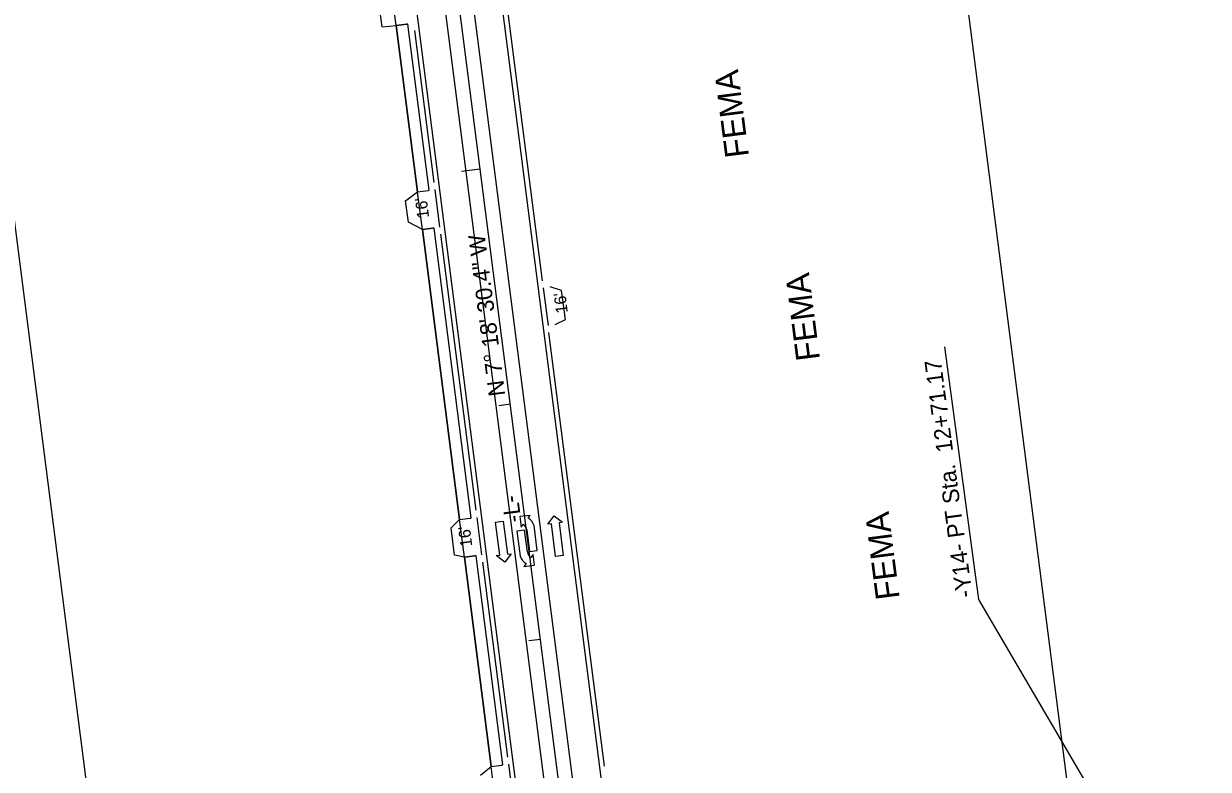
# Model space of a CAD drawing. Extents: x 2367848 to 2369479, y 800728 to 808616.
# Drawn here: x 2368272.3 to 2368772.3, y 807053 to 807367.5 of the extents above; entities that cross this region are included whole.
import ezdxf

# ---------------------------------------------------------------- set-up
doc = ezdxf.new("R2010")
doc.units = 0
for name, color, linetype in [('Default', 7, 'Continuous'), ('Prop Conc 2ft 6in Curb and Gutter', 7, 'Continuous'), ('Prop Conc 4in Sidewalk', 7, 'Continuous'), ('Prop Conc Drive Radius Type', 7, 'Continuous'), ('Prop Conc Driveway', 7, 'Continuous'), ('Prop Dimension', 7, 'Continuous'), ('Prop EOT', 7, 'Continuous'), ('Prop Horizontal Alignment', 7, 'Continuous'), ('Prop Horizontal Alignment Direction Label', 7, 'Continuous'), ('Prop Horizontal Alignment Station Label', 7, 'Continuous'), ('Prop Horizontal Alignment Tick Large', 7, 'Continuous'), ('Prop Horizontal Alignment Tick Small', 7, 'Continuous'), ('Prop Lane Arrow CELL', 7, 'Continuous'), ('Prop Lane Lines', 7, 'Continuous'), ('Prop Shade Light', 7, 'Continuous')]:
    doc.layers.add(name, color=color, linetype=linetype)

msp = doc.modelspace()

# ---------------------------------------------------------------- linework, layer by layer
at = {"layer": 'Default'}
msp.add_lwpolyline([(2368314.5, 806925.55), (2368228.68, 807594.69), (2368635.74, 807646.9), (2368721.56, 806977.76)], close=True, dxfattribs=at)
at = {"layer": 'Prop Conc 2ft 6in Curb and Gutter'}
for p, q in [((2368491.22, 807259.04), (2368456.92, 807526.55)), ((2368445.58, 807300.48), (2368437.35, 807364.66)), ((2368463.31, 807162.25), (2368448.38, 807278.66)), ((2368517.47, 807054.39), (2368494.02, 807237.22)), ((2368476.66, 807058.15), (2368466.11, 807140.42))]:
    msp.add_line(p, q, dxfattribs=at)
at = {"layer": 'Prop Conc 4in Sidewalk'}
for p, q in [((2368438.52, 807296.55), (2368429.53, 807366.69)), ((2368443.48, 807297.23), (2368434.49, 807367.28)), ((2368456.25, 807158.32), (2368440.56, 807280.68)), ((2368461.21, 807159), (2368445.52, 807281.27)), ((2368474.56, 807054.9), (2368463.25, 807143.04)), ((2368469.6, 807054.22), (2368458.29, 807142.45))]:
    msp.add_line(p, q, dxfattribs=at)
for centre, radius, start, end in [((2368434.36, 807364.27), 3.01, 87.523, 97.087), ((2368442.6, 807300.1), 3, 277.346, 286.9353), ((2368445.39, 807278.27), 3.01, 87.523, 97.087), ((2368460.33, 807161.87), 3, 277.3461, 286.91), ((2368463.12, 807140.03), 3.01, 87.5479, 97.0866), ((2368473.68, 807057.77), 3, 277.346, 286.9289)]:
    msp.add_arc(centre, radius, start, end, dxfattribs=at)
at = {"layer": 'Prop Conc Drive Radius Type'}
for p, q in [((2368448, 807281.64), (2368445.96, 807297.51)), ((2368491.61, 807256.07), (2368493.64, 807240.2)), ((2368465.73, 807143.4), (2368463.69, 807159.27)), ((2368479.08, 807039.31), (2368477.04, 807055.18))]:
    msp.add_line(p, q, dxfattribs=at)
at = {"layer": 'Prop Conc Driveway'}
for p, q in [((2368423.55, 807366.13), (2368420.61, 807389.08)), ((2368429.53, 807366.69), (2368426.48, 807390.49)), ((2368423.55, 807366.13), (2368429.53, 807366.69)), ((2368429.53, 807366.69), (2368433.99, 807367.26)), ((2368438.52, 807296.55), (2368442.99, 807297.12)), ((2368440.56, 807280.68), (2368438.52, 807296.55)), ((2368440.56, 807280.68), (2368445.02, 807281.25)), ((2368456.25, 807158.32), (2368460.72, 807158.89)), ((2368458.29, 807142.45), (2368456.25, 807158.32)), ((2368458.29, 807142.45), (2368462.75, 807143.02)), ((2368465.12, 807050.56), (2368469.6, 807054.22)), ((2368469.6, 807054.22), (2368474.07, 807054.8)), ((2368471.64, 807038.35), (2368469.6, 807054.22))]:
    msp.add_line(p, q, dxfattribs=at)
at = {"layer": 'Prop EOT'}
for p, q in [((2368533.61, 806912.84), (2368454.93, 807526.29)), ((2368497.9, 806908.26), (2368419.22, 807521.71)), ((2368433.45, 807292.78), (2368438.52, 807296.55)), ((2368434.77, 807283.78), (2368433.45, 807292.78)), ((2368440.56, 807280.68), (2368434.77, 807283.78)), ((2368499.23, 807254.99), (2368494.58, 807256.45)), ((2368500.92, 807242.66), (2368499.23, 807254.99)), ((2368496.62, 807240.58), (2368500.92, 807242.66)), ((2368456.25, 807158.32), (2368452.78, 807154.9)), ((2368454.16, 807143.27), (2368452.78, 807154.9)), ((2368458.29, 807142.45), (2368454.16, 807143.27))]:
    msp.add_line(p, q, dxfattribs=at)
at = {"layer": 'Prop Horizontal Alignment'}
msp.add_line((2368515.76, 806910.55), (2368437.08, 807524), dxfattribs=at)
at = {"layer": 'Prop Horizontal Alignment Station Label'}
for p, q in [((2368675.39, 807124.6), (2368661.07, 807231.23)), ((2368772.29, 806959.42), (2368675.39, 807124.6))]:
    msp.add_line(p, q, dxfattribs=at)
at = {"layer": 'Prop Horizontal Alignment Tick Large'}
msp.add_line((2368465.02, 807306.15), (2368457.08, 807305.13), dxfattribs=at)
at = {"layer": 'Prop Horizontal Alignment Tick Small'}
for p, q in [((2368477.74, 807206.96), (2368472.78, 807206.33)), ((2368490.46, 807107.78), (2368485.5, 807107.14))]:
    msp.add_line(p, q, dxfattribs=at)
at = {"layer": 'Prop Lane Arrow CELL'}
for p, q in [((2368486.1, 807160.1), (2368481.73, 807159.59)), ((2368481.73, 807159.59), (2368482.25, 807155.12)), ((2368485.19, 807158.92), (2368486.1, 807160.1)), ((2368493.52, 807156.41), (2368496.19, 807159.93)), ((2368496.19, 807159.93), (2368499.77, 807157.21)), ((2368471.46, 807157.19), (2368474.73, 807157.61)), ((2368473.24, 807143.31), (2368471.46, 807157.19)), ((2368474.73, 807157.61), (2368476.51, 807143.73)), ((2368483.73, 807153.79), (2368480.46, 807153.37)), ((2368480.46, 807153.37), (2368481.8, 807142.91)), ((2368482.25, 807155.12), (2368483.16, 807156.29)), ((2368484.9, 807144.72), (2368483.73, 807153.79)), ((2368484.62, 807153.96), (2368485.78, 807144.88)), ((2368489.06, 807145.3), (2368487.72, 807155.77)), ((2368495.01, 807156.6), (2368493.52, 807156.41)), ((2368496.79, 807142.72), (2368495.01, 807156.6)), ((2368499.77, 807157.21), (2368498.28, 807157.02)), ((2368498.28, 807157.02), (2368500.06, 807143.14)), ((2368471.75, 807143.12), (2368473.24, 807143.31)), ((2368475.32, 807140.4), (2368471.75, 807143.12)), ((2368478, 807143.92), (2368475.32, 807140.4)), ((2368476.51, 807143.73), (2368478, 807143.92)), ((2368485.78, 807144.88), (2368489.06, 807145.3)), ((2368487.27, 807143.56), (2368486.36, 807142.38)), ((2368487.84, 807139.1), (2368487.27, 807143.56)), ((2368500.06, 807143.14), (2368496.79, 807142.72)), ((2368484.33, 807139.76), (2368483.42, 807138.53)), ((2368483.42, 807138.53), (2368487.84, 807139.1))]:
    msp.add_line(p, q, dxfattribs=at)
for centre, radius, start, end in [((2368482.68, 807154.32), 5.25, 15.9845, 61.2962), ((2368481.39, 807153.55), 3.27, 7.3084, 56.9666), ((2368488.16, 807145.11), 3.27, 187.3084, 236.9666), ((2368486.87, 807144.34), 5.25, 195.9845, 241.2962)]:
    msp.add_arc(centre, radius, start, end, dxfattribs=at)
at = {"layer": 'Prop Lane Lines'}
for p, q in [((2368509.8, 806909.79), (2368431.13, 807523.24)), ((2368521.71, 806911.32), (2368443.03, 807524.77))]:
    msp.add_line(p, q, dxfattribs=at)
at = {"layer": 'Prop Shade Light'}
for p, q in [((2368433.99, 807367.26), (2368429.53, 807366.69)), ((2368429.53, 807366.69), (2368438.52, 807296.55)), ((2368443.48, 807297.23), (2368434.49, 807367.28)), ((2368438.52, 807296.55), (2368442.99, 807297.12)), ((2368445.02, 807281.25), (2368440.56, 807280.68)), ((2368440.56, 807280.68), (2368456.25, 807158.32)), ((2368461.21, 807159), (2368445.52, 807281.27)), ((2368456.25, 807158.32), (2368460.72, 807158.89)), ((2368462.75, 807143.02), (2368458.29, 807142.45)), ((2368474.56, 807054.9), (2368463.25, 807143.04)), ((2368458.29, 807142.45), (2368469.6, 807054.22)), ((2368469.6, 807054.22), (2368474.07, 807054.8))]:
    msp.add_line(p, q, dxfattribs=at)
for centre, radius, start, end in [((2368434.36, 807364.27), 3.01, 87.523, 97.087), ((2368442.6, 807300.1), 3, 277.346, 286.9353), ((2368445.39, 807278.27), 3.01, 87.523, 97.087), ((2368460.33, 807161.87), 3, 277.3461, 286.91), ((2368463.12, 807140.03), 3.01, 87.5479, 97.0866), ((2368473.68, 807057.77), 3, 277.346, 286.9289)]:
    msp.add_arc(centre, radius, start, end, dxfattribs=at)

# ---------------------------------------------------------------- texts
at = {"layer": 'Prop Dimension'}
for s, height, rotation, p in [('FEMA', 10, 97.2784, (2368578.46, 807311.6)), ("16'", 5, 97.3084, (2368443.46, 807285.72)), ('FEMA', 10, 97.2784, (2368608.43, 807225.94)), ("16'", 5, 97.3084, (2368501.99, 807245.63)), ('FEMA', 10, 97.2784, (2368642.06, 807125.19)), ("16'", 5, 97.3084, (2368461.68, 807147.12))]:
    msp.add_text(s, height=height, rotation=rotation, dxfattribs=at).set_placement(p)
at = {"layer": 'Prop Horizontal Alignment Direction Label'}
msp.add_text('N 7%%d 18\' 30.4" W', height=7, rotation=97.3084, dxfattribs=at).set_placement((2368475.6, 807210.78))
at = {"layer": 'Prop Horizontal Alignment Station Label'}
for s, rotation, p in [('-Y14- PT Sta.  12+71.17', 97.6477, (2368672.85, 807125.84)), ('-L-', 97.3084, (2368482.36, 807157.55))]:
    msp.add_text(s, height=7, rotation=rotation, dxfattribs=at).set_placement(p)

doc.saveas('drawing.dxf')
